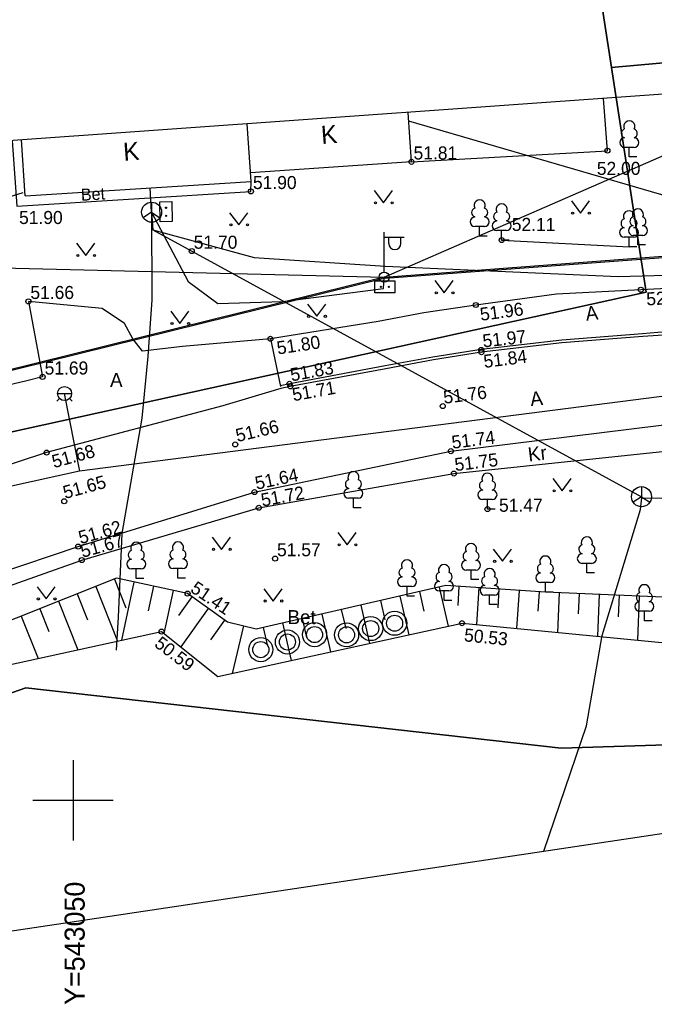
# Model space of a CAD drawing. Extents: x 542320 to 543602, y 6558748 to 6559969.
# Drawn here: x 543047.34 to 543078.97, y 6559789.84 to 6559838.87 of the extents above; entities that cross this region are included whole.
import ezdxf

# ---------------------------------------------------------------- set-up
doc = ezdxf.new("R2010")
doc.units = 0
for name, color, linetype in [('AED', 7, 'Continuous'), ('HALJASTUS', 7, 'Continuous'), ('HOONE', 7, 'Continuous'), ('HOONEDET', 7, 'Continuous'), ('KORGUS-EH2000', 7, 'Continuous'), ('KTRASS', 7, 'Continuous'), ('mootpiir', 7, 'Continuous'), ('MPOHULIIN', 7, 'Continuous'), ('PIIR', 7, 'Continuous'), ('POST', 7, 'Continuous'), ('PUU', 7, 'Continuous'), ('RAJATIS', 7, 'Continuous'), ('RELJEEF', 7, 'Continuous'), ('SIKAEV', 7, 'Continuous'), ('SIOHULIIN', 7, 'Continuous'), ('SIRAJATIS', 7, 'Continuous'), ('SITRASS', 7, 'Continuous'), ('TEE', 7, 'Continuous'), ('VEEKOGU', 7, 'Continuous'), ('VKAEV', 7, 'Continuous'), ('VORK', 7, 'Continuous'), ('VTRASS', 7, 'Continuous')]:
    doc.layers.add(name, color=color, linetype=linetype)

# ---------------------------------------------------------------- blocks, each defined once
blk = doc.blocks.new('VKORIS')
for p, q in [((0, 4), (0, -4)), ((-4, 0), (4, 0))]:
    blk.add_line(p, q)
blk = doc.blocks.new('SIKAEV')
for p, q in [((0, 1), (0, 0)), ((0, 0), (-0.83, -0.55)), ((0, 0), (0.83, -0.55))]:
    blk.add_line(p, q)
blk.add_circle((0, 0), 1)
blk = doc.blocks.new('SIKAPP')
blk.add_lwpolyline([(-1, 0.6), (1, 0.6), (1, -0.6), (-1, -0.6)], close=True)
for centre, radius in [((-0.4, 0), 0.0608), ((-0.4, 0), 0.0581), ((-0.4, 0), 0.0553), ((-0.4, 0), 0.0526), ((-0.4, 0), 0.0499), ((-0.4, 0), 0.0472), ((-0.4, 0), 0.0444), ((-0.4, 0), 0.0417), ((-0.4, 0), 0.039), ((-0.4, 0), 0.0363), ((-0.4, 0), 0.0335), ((-0.4, 0), 0.0308), ((-0.4, 0), 0.0281), ((-0.4, 0), 0.0254), ((-0.4, 0), 0.0226), ((-0.4, 0), 0.0199), ((-0.4, 0), 0.0172), ((-0.4, 0), 0.0145), ((-0.4, 0), 0.0117), ((-0.4, 0), 0.00902), ((-0.4, 0), 0.0063), ((-0.4, 0), 0.00358), ((-0.4, 0), 0.000852), ((0.4, 0), 0.0608), ((0.4, 0), 0.0581), ((0.4, 0), 0.0553), ((0.4, 0), 0.0526), ((0.4, 0), 0.0499), ((0.4, 0), 0.0472), ((0.4, 0), 0.0444), ((0.4, 0), 0.0417), ((0.4, 0), 0.039), ((0.4, 0), 0.0363), ((0.4, 0), 0.0335), ((0.4, 0), 0.0308), ((0.4, 0), 0.0281), ((0.4, 0), 0.0254), ((0.4, 0), 0.0226), ((0.4, 0), 0.0199), ((0.4, 0), 0.0172), ((0.4, 0), 0.0145), ((0.4, 0), 0.0117), ((0.4, 0), 0.00902), ((0.4, 0), 0.0063), ((0.4, 0), 0.00358), ((0.4, 0), 0.000852)]:
    blk.add_circle(centre, radius)
blk = doc.blocks.new('VESIIB')
for p, q in [((-0.7, 0), (0.7, 0)), ((-0.495, -0.495), (-0.774, -0.774)), ((0.495, -0.495), (0.774, -0.774))]:
    blk.add_line(p, q)
blk.add_circle((0, 0), 0.7)
blk = doc.blocks.new('PUPOST')
blk.add_circle((0, 0), 0.5)
blk = doc.blocks.new('LEHTP1')
for p, q in [((0.48, 0.95), (-0.48, 0.95)), ((0, 0), (0, 0.95)), ((0.76, 0), (0, 0))]:
    blk.add_line(p, q)
for centre, radius, start, end in [((0, 3.04), 0.554, 332.5799, 207.4201), ((-0.34, 2.345), 0.465, 109.02174, 253.14154), ((0.34, 2.345), 0.465, 286.85082, 70.98591), ((-0.475, 1.425), 0.475, 90.0016, 269.3953), ((0.475, 1.425), 0.475, 270.6047, 89.9984)]:
    blk.add_arc(centre, radius, start, end)
blk = doc.blocks.new('MURU')
for p, q in [((-0.927, 1.213), (0, 0)), ((0, 0), (0.891, 1.213))]:
    blk.add_line(p, q)
for centre in [(-0.802, 0), (0.856, 0)]:
    blk.add_circle(centre, 0.11)
blk = doc.blocks.new('VAPOST')
for p, q in [((0, 0.5), (0, 4.5)), ((0, 4), (2, 4)), ((0.453, 3.358), (0.453, 4)), ((1.679, 3.358), (1.679, 4))]:
    blk.add_line(p, q)
blk.add_arc((1.066, 3.358), 0.613, 180, 0)
blk = doc.blocks.new('RING02')
blk.add_circle((0, 0), 0.25)

msp = doc.modelspace()

# ---------------------------------------------------------------- linework, layer by layer
at = {"layer": 'AED'}
for points in [[(543066.871, 6559831.793), (543076.63, 6559832.348), (543076.437, 6559834.946)], [(543047.506, 6559830.252), (543031.229, 6559825.246), (543011.07, 6559819.081), (543008.098, 6559818.456), (543001.026, 6559817.957)]]:
    msp.add_lwpolyline(points, dxfattribs=at)
at = {"layer": 'HALJASTUS'}
msp.add_lwpolyline([(543071.361, 6559827.898), (543077.712, 6559827.562)], dxfattribs=at)
at = {"layer": 'HOONE'}
for points in [[(543066.871, 6559831.793), (543066.704, 6559834.255)], [(543058.88, 6559830.819), (543058.685, 6559833.686)], [(543047.613, 6559830.097), (543047.424, 6559832.887)], [(543066.871, 6559831.793), (543058.851, 6559831.249)], [(543047.613, 6559830.097), (543058.88, 6559830.819), (543058.88, 6559830.819), (543058.88, 6559830.819)]]:
    msp.add_lwpolyline(points, dxfattribs=at)
at = {"layer": 'HOONEDET'}
msp.add_lwpolyline([(543046.969, 6559832.855), (543047.191, 6559829.582), (543058.866, 6559830.32), (543058.88, 6559830.819)], dxfattribs=at)
at = {"layer": 'KTRASS'}
msp.add_lwpolyline([(543066.724, 6559833.829), (543079.729, 6559830.052), (543083.997, 6559832.232)], dxfattribs=at)
at = {"layer": 'mootpiir'}
msp.add_lwpolyline([(543090.147, 6559835.076), (543086.631, 6559835.669), (543046.075, 6559832.791), (542960.087, 6559816.316), (542958.508, 6559813.972), (542958.352, 6559813.615), (542958.072, 6559811.407), (542958.097, 6559811.262), (542958.667, 6559807.427), (542958.816, 6559803.633), (542958.4, 6559802.481), (542958.245, 6559799.726), (542966.032, 6559797.567), (543032.743, 6559791.379), (543093.076, 6559800.414), (543094.129, 6559807.466), (543092.769, 6559812.064), (543093.098, 6559815.823), (543092.736, 6559818.278), (543092.585, 6559819.369), (543092.195, 6559821.683), (543090.475, 6559823.796), (543090.459, 6559823.908), (543090.312, 6559826.089)], close=True, dxfattribs=at)
at = {"layer": 'MPOHULIIN'}
for points in [[(543065.505, 6559826.048), (543106.507, 6559829.132)], [(543065.505, 6559826.048), (543039.523, 6559819.62), (543009.299, 6559818.737), (542961.154, 6559815.297)]]:
    msp.add_lwpolyline(points, dxfattribs=at)
at = {"layer": 'PIIR'}
for points in [[(543109.13, 6559904.85), (543125.66, 6559869.87), (543123.8, 6559868.51), (543128.91, 6559853.92), (543128.04, 6559829.23), (543085.54, 6559829.09), (543087.22, 6559837.42), (543076.83, 6559836.49), (543069.03, 6559887.03), (543109.13, 6559904.85)], [(542995.62, 6559810.72), (542999.42, 6559826.35), (543006.28, 6559854.63), (543022.96, 6559853.69), (543024.02, 6559863.81), (543009.03, 6559865.93), (543011.73, 6559877.03), (543035.19, 6559883.28), (543069.03, 6559887.03), (543076.83, 6559836.49), (543078.56, 6559825.31), (543011.79, 6559810.61), (542995.62, 6559810.72)], [(543110.35, 6559810.08), (543085.87, 6559802.96), (543074.33, 6559802.6), (543047.65, 6559805.6), (543029.51, 6559799.26), (543012.82, 6559798.86), (543001.44, 6559800.31), (542966.22, 6559801.72), (542946.49, 6559799.49), (542945.79, 6559811), (542995.62, 6559810.72), (543011.79, 6559810.61), (543078.56, 6559825.31), (543076.83, 6559836.49), (543087.22, 6559837.42), (543085.54, 6559829.09), (543128.04, 6559829.23)], [(543012.82, 6559798.86), (543029.51, 6559799.26), (543047.65, 6559805.6), (543074.33, 6559802.6), (543085.87, 6559802.96), (543110.35, 6559810.08)]]:
    msp.add_lwpolyline(points, dxfattribs=at)
at = {"layer": 'RAJATIS'}
for centre, radius in [((543066.028, 6559808.817), 0.6), ((543062.038, 6559808.25), 0.6), ((543063.633, 6559808.24), 0.6), ((543064.834, 6559808.551), 0.6), ((543064.834, 6559808.551), 0.4), ((543066.028, 6559808.817), 0.4), ((543060.686, 6559807.883), 0.6), ((543062.038, 6559808.25), 0.4), ((543063.633, 6559808.24), 0.4), ((543059.358, 6559807.503), 0.6), ((543059.358, 6559807.503), 0.4), ((543060.686, 6559807.883), 0.4)]:
    msp.add_circle(centre, radius, dxfattribs=at)
at = {"layer": 'RELJEEF'}
for points in [[(543092.769, 6559812.064), (543089.999, 6559809.142), (543084.85, 6559808.813), (543080.585, 6559810.073), (543073.543, 6559810.368), (543068.572, 6559810.695), (543059.132, 6559808.528), (543057.697, 6559808.874), (543055.711, 6559810.294), (543052.162, 6559811.058), (543042.149, 6559807.07), (543028.907, 6559800.786), (543017.173, 6559800.875), (543003.671, 6559801.671), (542989.215, 6559802.013), (542980.978, 6559802.587), (542969.167, 6559801.941), (542958.4, 6559802.481)], [(543052.066, 6559811.02), (543052.639, 6559809.58)], [(543053.038, 6559810.869), (543052.414, 6559807.967)], [(543050.208, 6559810.28), (543050.719, 6559808.995)], [(543051.137, 6559810.65), (543052.222, 6559807.926)], [(543054.016, 6559810.659), (543053.751, 6559809.43)], [(543054.993, 6559810.448), (543054.533, 6559808.308)], [(543067.269, 6559810.396), (543067.491, 6559809.426)], [(543068.243, 6559810.62), (543068.691, 6559808.669)], [(543069.234, 6559810.651), (543069.171, 6559809.706)], [(543070.231, 6559810.586), (543070.111, 6559808.751)], [(543071.229, 6559810.52), (543071.168, 6559809.588)], [(543072.227, 6559810.455), (543072.102, 6559808.559)], [(543073.225, 6559810.389), (543073.162, 6559809.426)], [(543074.224, 6559810.339), (543074.141, 6559808.362)], [(543075.223, 6559810.298), (543075.18, 6559809.282)], [(543049.279, 6559809.91), (543050.24, 6559807.496)], [(543055.927, 6559810.139), (543055.257, 6559809.202)], [(543065.32, 6559809.948), (543065.54, 6559808.989)], [(543066.294, 6559810.172), (543066.737, 6559808.243)], [(543076.222, 6559810.256), (543076.134, 6559808.17)], [(543077.221, 6559810.214), (543077.176, 6559809.144)], [(543078.22, 6559810.172), (543078.128, 6559807.978)], [(543048.35, 6559809.54), (543048.799, 6559808.41)], [(543056.741, 6559809.558), (543055.369, 6559807.639)], [(543062.396, 6559809.277), (543062.829, 6559807.39)], [(543063.37, 6559809.501), (543063.588, 6559808.552)], [(543064.345, 6559809.725), (543064.783, 6559807.816)], [(543047.421, 6559809.17), (543048.259, 6559807.065)], [(543057.554, 6559808.976), (543056.853, 6559807.995)], [(543060.446, 6559808.83), (543060.875, 6559806.963)], [(543061.421, 6559809.053), (543061.636, 6559808.115)], [(543058.499, 6559808.681), (543057.93, 6559806.321)], [(543059.472, 6559808.606), (543059.685, 6559807.678)]]:
    msp.add_lwpolyline(points, dxfattribs=at)
at = {"layer": 'SIOHULIIN'}
for points in [[(542986.521, 6559827.98), (543065.505, 6559826.048), (543087.322, 6559835.539)], [(543065.564, 6559825.995), (543106.476, 6559829.043)], [(543065.564, 6559825.995), (543039.532, 6559819.569)]]:
    msp.add_lwpolyline(points, dxfattribs=at)
at = {"layer": 'SITRASS'}
for points in [[(543053.917, 6559829.286), (543053.839, 6559830.496)], [(543053.917, 6559829.286), (543053.974, 6559828.4), (543059.028, 6559827.021), (543065.55, 6559826.599), (543077.169, 6559826.084), (543081.941, 6559826.218), (543085.572, 6559826.758), (543088.386, 6559828.092), (543090.244, 6559829.795)], [(543053.917, 6559829.286), (543053.928, 6559824.915), (543053.733, 6559822.103), (543053.425, 6559819.033), (543052.433, 6559813.293), (543052.253, 6559809.126), (543052.149, 6559807.474)], [(543053.917, 6559829.286), (543055.735, 6559825.832), (543057.217, 6559824.734), (543060.446, 6559824.838), (543065.471, 6559825.493), (543065.505, 6559826.048)], [(543053.974, 6559828.4), (543078.331, 6559815.119)], [(543078.354, 6559815.059), (543079.334, 6559815.049), (543082.664, 6559815.311), (543092.997, 6559816.527)], [(543073.462, 6559797.474), (543075.596, 6559803.704), (543076.366, 6559808.208), (543078.276, 6559814.479), (543078.354, 6559815.059)]]:
    msp.add_lwpolyline(points, dxfattribs=at)
at = {"layer": 'TEE'}
for points in [[(543059.834, 6559822.98), (543055.462, 6559822.59), (543053.469, 6559822.365), (543052.979, 6559822.974), (543052.571, 6559823.736), (543051.452, 6559824.494), (543047.774, 6559824.845), (543048.484, 6559821.084), (543047.702, 6559820.894), (543044.868, 6559820.228), (543044.116, 6559827.845), (543040.658, 6559826.72), (543041.446, 6559819.386), (543038.689, 6559818.611), (543035.622, 6559817.731), (543035.443, 6559815.688), (543035.967, 6559812.959)], [(543090.312, 6559826.089), (543086.383, 6559826.03), (543081.905, 6559825.596), (543078.303, 6559825.425), (543074.1, 6559825.199), (543070.074, 6559824.663), (543067.487, 6559824.275), (543065.214, 6559823.846), (543059.834, 6559822.98), (543060.342, 6559820.61)], [(543090.467, 6559823.936), (543086.5, 6559823.721), (543083.992, 6559823.574), (543081.981, 6559823.449), (543079.149, 6559823.293), (543078.382, 6559823.232), (543074.353, 6559822.916), (543070.335, 6559822.452), (543067.933, 6559822.071), (543065.56, 6559821.631), (543060.801, 6559820.746), (543060.324, 6559820.64)], [(543090.475, 6559823.796), (543086.508, 6559823.581), (543084, 6559823.434), (543081.989, 6559823.309), (543079.158, 6559823.153), (543078.393, 6559823.092), (543074.367, 6559822.777), (543070.354, 6559822.313), (543067.957, 6559821.933), (543065.586, 6559821.493), (543060.829, 6559820.609), (543060.355, 6559820.503)], [(543060.355, 6559820.503), (543057.468, 6559819.65), (543048.685, 6559817.313), (543040.045, 6559814.486), (543035.967, 6559812.959), (543031.279, 6559811.296), (543026.934, 6559810.533), (543016.801, 6559809.157), (543007.227, 6559808.975), (542997.411, 6559809.534), (542988.775, 6559810.531)], [(542958.816, 6559803.633), (542969.162, 6559804.651), (542980.925, 6559804.056), (542987.926, 6559803.597), (542997.513, 6559803.059), (543007.107, 6559803.04), (543017.723, 6559803.474), (543028.051, 6559804.793), (543037.828, 6559808.06), (543042.163, 6559809.918), (543050.261, 6559812.635), (543059.043, 6559815.346), (543068.835, 6559817.386), (543079.318, 6559818.681), (543092.585, 6559819.369)], [(542997.513, 6559803.059), (543007.066, 6559802.483), (543017.906, 6559802.775), (543028.213, 6559804.2), (543038.057, 6559807.69), (543042.598, 6559809.18), (543050.432, 6559811.965), (543059.255, 6559814.566), (543068.982, 6559816.272), (543079.524, 6559817.38), (543092.736, 6559818.278)]]:
    msp.add_lwpolyline(points, dxfattribs=at)
at = {"layer": 'VEEKOGU'}
msp.add_lwpolyline([(542958.245, 6559799.726), (542969.193, 6559799.837), (542980.767, 6559800.499), (542989.253, 6559800.672), (543003.747, 6559800.309), (543017.23, 6559799.73), (543028.875, 6559799.639), (543042.762, 6559805.872), (543054.415, 6559808.402), (543057.212, 6559806.164), (543069.386, 6559808.821), (543079.867, 6559807.81), (543085.814, 6559807.064), (543094.129, 6559807.466)], dxfattribs=at)
at = {"layer": 'VTRASS'}
for points in [[(543084.909, 6559820.815), (543050.322, 6559816.388), (543018.303, 6559809.334), (542995.998, 6559810.646), (542958.256, 6559810.221)], [(543049.553, 6559820.249), (543050.322, 6559816.388)]]:
    msp.add_lwpolyline(points, dxfattribs=at)

# ---------------------------------------------------------------- block references
at = {"layer": 'HALJASTUS', "xscale": 0.5, "yscale": 0.5}
for p in [(543065.475, 6559829.752), (543075.299, 6559829.237), (543058.268, 6559828.654), (543050.642, 6559827.13), (543068.503, 6559825.27), (543062.149, 6559824.104), (543055.33, 6559823.745), (543074.381, 6559815.412), (543063.665, 6559812.723), (543057.401, 6559812.495), (543071.41, 6559811.904), (543048.669, 6559810.03), (543059.975, 6559809.923)]:
    msp.add_blockref('MURU', p, dxfattribs=at)
at = {"layer": 'KORGUS-EH2000', "xscale": 0.5, "yscale": 0.5}
for p in [(543076.63, 6559832.348), (543066.871, 6559831.793), (543058.866, 6559830.32), (543071.361, 6559827.898), (543055.916, 6559827.348), (543078.303, 6559825.425), (543047.774, 6559824.845), (543070.074, 6559824.663), (543059.834, 6559822.98), (543070.345, 6559822.429), (543070.354, 6559822.313), (543048.484, 6559821.084), (543060.786, 6559820.741), (543060.829, 6559820.609), (543068.423, 6559819.629), (543058.087, 6559817.72), (543048.685, 6559817.313), (543068.835, 6559817.386), (543068.982, 6559816.272), (543059.043, 6559815.346), (543049.56, 6559814.892), (543059.255, 6559814.566), (543070.655, 6559814.5), (543050.261, 6559812.635), (543050.432, 6559811.965), (543060.067, 6559812.036), (543055.711, 6559810.294), (543069.386, 6559808.821), (543054.415, 6559808.402)]:
    msp.add_blockref('RING02', p, dxfattribs=at)
at = {"layer": 'POST', "xscale": 0.5, "yscale": 0.5}
for name in ['VAPOST', 'PUPOST']:
    msp.add_blockref(name, (543065.505, 6559826.048), dxfattribs=at)
at = {"layer": 'PUU', "xscale": 0.5, "yscale": 0.5}
for p in [(543077.72, 6559832.036), (543070.264, 6559828.097), (543071.361, 6559827.898), (543077.712, 6559827.562), (543078.151, 6559827.654), (543063.975, 6559814.57), (543070.655, 6559814.5), (543053.15, 6559811.05), (543055.227, 6559811.067), (543069.838, 6559810.99), (543075.607, 6559811.324), (543066.646, 6559810.171), (543068.493, 6559809.948), (543073.543, 6559810.368), (543070.759, 6559809.743), (543078.477, 6559808.941)]:
    msp.add_blockref('LEHTP1', p, dxfattribs=at)
at = {"layer": 'SIKAEV', "xscale": 0.5, "yscale": 0.5}
for p in [(543053.917, 6559829.286), (543078.331, 6559815.119)]:
    msp.add_blockref('SIKAEV', p, dxfattribs=at)
at = {"layer": 'SIRAJATIS', "xscale": 0.5000000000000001, "yscale": 0.4999999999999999, "rotation": 91.20702171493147}
msp.add_blockref('SIKAPP', (543054.635, 6559829.307), dxfattribs=at)
at = {"layer": 'SIRAJATIS', "xscale": 0.5, "yscale": 0.5}
msp.add_blockref('SIKAPP', (543065.538, 6559825.569), dxfattribs=at)
at = {"layer": 'VKAEV', "xscale": 0.5, "yscale": 0.5}
msp.add_blockref('VESIIB', (543049.576, 6559820.254), dxfattribs=at)
at = {"layer": 'VORK', "xscale": 0.5, "yscale": 0.5}
msp.add_blockref('VKORIS', (543050, 6559800), dxfattribs=at)

# ---------------------------------------------------------------- texts
at = {"layer": 'HOONE'}
for p in [(543062.393, 6559832.678), (543052.533, 6559831.84)]:
    msp.add_text('K', height=0.9, rotation=4.2597, dxfattribs=at).set_placement(p)
at = {"layer": 'HOONEDET'}
msp.add_text('Bet', height=0.6, rotation=3.3898, dxfattribs=at).set_placement((543050.408, 6559829.85))
at = {"layer": 'KORGUS-EH2000'}
for s, p in [('51.81', (543066.971, 6559831.91)), ('52.00', (543076.105, 6559831.141)), ('51.90', (543058.966, 6559830.437)), ('51.90', (543047.311, 6559828.696)), ('52.11', (543071.867, 6559828.351)), ('51.70', (543056.016, 6559827.465)), ('51.66', (543047.874, 6559824.962)), ('51.69', (543048.584, 6559821.201)), ('51.47', (543071.23, 6559814.368)), ('51.57', (543060.167, 6559812.153))]:
    msp.add_text(s, height=0.65, dxfattribs=at).set_placement(p)
for s, rotation, p in [('52.16', 2.9274, (543078.587, 6559824.64)), ('51.96', 7.5583, (543070.326, 6559823.872)), ('51.80', 8.3269, (543060.205, 6559822.197)), ('51.97', 6.2917, (543070.447, 6559822.546)), ('51.84', 7.0466, (543070.499, 6559821.529)), ('51.83', 10.2056, (543060.889, 6559820.858)), ('51.71', 9.9652, (543060.983, 6559819.871)), ('51.76', 7.0466, (543068.496, 6559819.744)), ('51.66', 13.168, (543058.191, 6559817.837)), ('51.74', 7.0466, (543068.908, 6559817.501)), ('51.68', 15.2821, (543049.049, 6559816.537)), ('51.75', 7.0466, (543069.055, 6559816.387)), ('51.65', 15.2821, (543049.603, 6559815.001)), ('51.64', 11.799, (543059.146, 6559815.463)), ('51.72', 10.4903, (543059.433, 6559814.622)), ('51.62', 15.2821, (543050.375, 6559812.755)), ('51.67', 15.2821, (543050.475, 6559812.074)), ('51.41', 325.9951, (543055.802, 6559810.414)), ('50.53', 354.1676, (543069.466, 6559807.921)), ('50.59', 322.5196, (543054.006, 6559807.699))]:
    msp.add_text(s, height=0.65, rotation=rotation, dxfattribs=at).set_placement(p)
at = {"layer": 'RAJATIS'}
msp.add_text('Bet', height=0.7, dxfattribs=at).set_placement((543060.689, 6559808.772))
at = {"layer": 'TEE'}
for s, rotation, p in [('A', 6.1983, (543075.581, 6559823.88)), ('A', 6.2453, (543072.82, 6559819.627)), ('Kr', 6.9919, (543072.715, 6559816.866))]:
    msp.add_text(s, height=0.7, rotation=rotation, dxfattribs=at).set_placement(p)
msp.add_text('A', height=0.7, dxfattribs=at).set_placement((543051.844, 6559820.584))
at = {"layer": 'VORK'}
msp.add_text('Y=543050', height=1, rotation=90, dxfattribs=at).set_placement((543050.581, 6559789.813))

doc.saveas('drawing.dxf')
